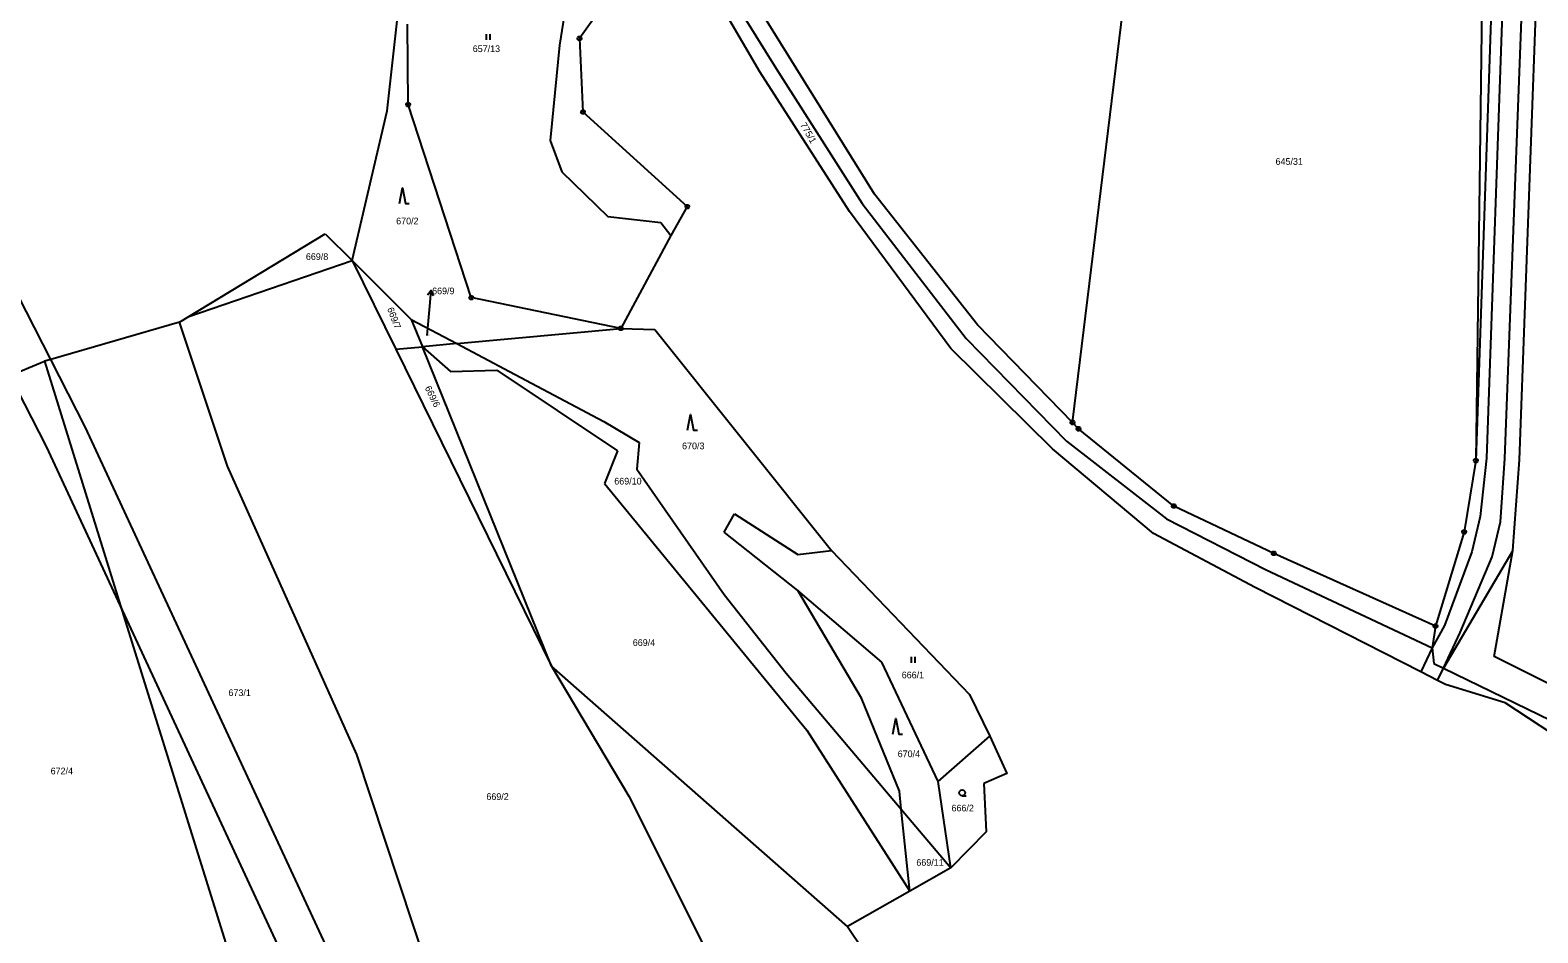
# Model space of a CAD drawing. Extents: x -694465 to -690527, y -983694 to -978978.
# Drawn here: x -693075.3 to -692691.9, y -983133.7 to -982904.1 of the extents above; entities that cross this region are included whole.
import ezdxf

# ---------------------------------------------------------------- set-up
doc = ezdxf.new("R2010")
doc.units = 0
for name, color, linetype in [('Vrstva 1', 7, 'Continuous'), ('Vrstva 16', 7, 'Continuous'), ('Vrstva 18', 7, 'Continuous'), ('Vrstva 24', 7, 'Continuous'), ('Vrstva 25', 7, 'Continuous'), ('Vrstva 29', 7, 'Continuous')]:
    doc.layers.add(name, color=color, linetype=linetype)

msp = doc.modelspace()

# ---------------------------------------------------------------- linework, layer by layer
at = {"layer": 'Vrstva 1'}
for points in [[(-692693.97, -982699.89), (-692705.02, -983012.99)], [(-692700.29, -983013.08), (-692688.43, -982700.11)], [(-693070.091, -982987.841), (-693099.057, -982931.222), (-693137.122, -982864.574), (-693163.283, -982827.058), (-693193.81, -982793.026), (-693210.393, -982777.707)], [(-692701.26, -982824.21), (-692707.71, -983013.6)], [(-692810.28, -983003.89), (-692790.65, -982843.64)], [(-692931.72, -982851.34), (-692940.69, -982907.88)], [(-692705.6, -982853.15), (-692707.71, -983013.6)], [(-692696.6, -983013.38), (-692690.84, -982855.94)], [(-692984.51, -982924.57), (-692976.98, -982856.48)], [(-692924.1, -982890.03), (-692935.65, -982906.19), (-692934.76, -982924.88), (-692908.22, -982948.98), (-692912.43, -982956.3)], [(-692721.73, -983067.37), (-692763.8, -983045.91), (-692789.68, -983032.11), (-692815.36, -983010.62), (-692841.17, -982985.05), (-692866.94, -982950.19), (-692889.77, -982914.71), (-692902.43, -982892.99), (-692902.38, -982890.58)], [(-692898.76, -982892.65), (-692885.65, -982913.87)], [(-692860.66, -982945.81), (-692894.16, -982891.71)], [(-692979.19, -982923.02), (-692979.38, -982902.54)], [(-692940.69, -982907.88), (-692943.13, -982932.17)], [(-692885.65, -982913.87), (-692863.75, -982948.19)], [(-692993.43, -982962.7), (-692984.51, -982924.57)], [(-692963.15, -982972.11), (-692979.19, -982923.02)], [(-692943.13, -982932.17), (-692940.11, -982940.11)], [(-692940.11, -982940.11), (-692928.43, -982951.47)], [(-692834.41, -982979.04), (-692860.66, -982945.81)], [(-692928.43, -982951.47), (-692914.99, -982952.98)], [(-692863.75, -982948.19), (-692837.29, -982982.54)], [(-692914.99, -982952.98), (-692912.43, -982956.3)], [(-693034.95, -982976.94), (-693000.27, -982955.89)], [(-693000.27, -982955.89), (-692993.43, -982962.7)], [(-692912.43, -982956.3), (-692925.14, -982979.97)], [(-693034.95, -982976.94), (-692993.43, -982962.7)], [(-692993.43, -982962.7), (-692982.37, -982985.27)], [(-692993.43, -982962.7), (-692978.41, -982977.65)], [(-692925.14, -982979.97), (-692963.15, -982972.11)], [(-693037.37, -982978.41), (-693070.091, -982987.841)], [(-693037.37, -982978.41), (-693034.95, -982976.94)], [(-693025.12, -983015.04), (-693037.37, -982978.41)], [(-692978.41, -982977.65), (-692975.59, -982984.64)], [(-692978.41, -982977.65), (-692966.79, -982983.83)], [(-692966.79, -982983.83), (-692925.14, -982979.97)], [(-692925.14, -982979.97), (-692916.48, -982980.27)], [(-692916.48, -982980.27), (-692871.52, -983036.45)], [(-692837.29, -982982.54), (-692811.77, -983008.68)], [(-692810.28, -983003.89), (-692834.41, -982979.04)], [(-692982.37, -982985.27), (-692975.59, -982984.64)], [(-692982.37, -982985.27), (-692942.79, -983065.9)], [(-692966.79, -982983.83), (-692975.59, -982984.64)], [(-692942.79, -983065.9), (-692975.59, -982984.64)], [(-692975.59, -982984.64), (-692968.44, -982990.89)], [(-692966.79, -982983.83), (-692953.44, -982990.93)], [(-693080.387, -982991.977), (-693071.72, -982988.31)], [(-693070.091, -982987.841), (-693071.72, -982988.31)], [(-693071.72, -982988.31), (-693052.335, -983050.557)], [(-692955.63, -983208.19), (-692974.61, -983181.207), (-693000.18, -983136.863), (-693061.246, -983005.207), (-693070.091, -982987.841)], [(-693052.335, -983050.557), (-693071.136, -983010.025), (-693080.387, -982991.977)], [(-692968.44, -982990.89), (-692956.67, -982990.6)], [(-692956.67, -982990.6), (-692925.97, -983011.1)], [(-692953.44, -982990.93), (-692929.45, -983003.63)], [(-692929.45, -983003.63), (-692920.47, -983008.96)], [(-692808.73, -983005.5), (-692810.28, -983003.89)], [(-692784.49, -983025.14), (-692808.73, -983005.5)], [(-692920.47, -983008.96), (-692921.02, -983015.79)], [(-692811.77, -983008.68), (-692786.33, -983028.43)], [(-692925.97, -983011.1), (-692929.24, -983019.41)], [(-692705.02, -983012.99), (-692706.63, -983027.79)], [(-692701.44, -983029.14), (-692700.29, -983013.08)], [(-692992.22, -983088.37), (-693025.12, -983015.04)], [(-692921.02, -983015.79), (-692898.84, -983047.69)], [(-692707.71, -983013.6), (-692710.68, -983031.75)], [(-692698.29, -983036.44), (-692696.6, -983013.38)], [(-692929.24, -983019.41), (-692877.84, -983082.18)], [(-692898.88, -983031.77), (-692896.22, -983027.16)], [(-692896.22, -983027.16), (-692880.11, -983037.51)], [(-692786.33, -983028.43), (-692761.22, -983041.31)], [(-692759.09, -983037.2), (-692784.49, -983025.14)], [(-692706.63, -983027.79), (-692708.76, -983036.78)], [(-692880.08, -983046.63), (-692898.88, -983031.77)], [(-692710.68, -983031.75), (-692717.94, -983055.71)], [(-692703.58, -983038.05), (-692701.44, -983029.14)], [(-692880.11, -983037.51), (-692871.52, -983036.45)], [(-692871.52, -983036.45), (-692836.46, -983073.11), (-692831.31, -983083.66)], [(-692717.94, -983055.71), (-692759.09, -983037.2)], [(-692698.29, -983036.44), (-692715.95, -983066.39)], [(-692708.76, -983036.78), (-692715.63, -983055.52)], [(-692711.7, -983057.33), (-692703.58, -983038.05)], [(-692703, -983063.4), (-692698.29, -983036.44)], [(-692761.22, -983041.31), (-692718.8, -983061.2)], [(-692898.84, -983047.69), (-692883.07, -983067.67)], [(-692858.79, -983064.9), (-692880.08, -983046.63)], [(-692863.92, -983074.03), (-692880.08, -983046.63)], [(-693012.431, -983136.594), (-693052.335, -983050.557)], [(-693052.335, -983050.557), (-693022.376, -983146.757)], [(-692715.63, -983055.52), (-692718.8, -983061.2)], [(-692717.94, -983055.71), (-692718.8, -983061.2)], [(-692715.95, -983066.39), (-692711.7, -983057.33)], [(-692718.8, -983061.2), (-692721.73, -983067.37)], [(-692718.8, -983061.2), (-692718.4, -983065.2)], [(-692942.79, -983065.9), (-692923.12, -983098.95)], [(-692867.48, -983132.13), (-692942.79, -983065.9)], [(-692844.44, -983095.26), (-692858.79, -983064.9)], [(-692718.4, -983065.2), (-692715.95, -983066.39)], [(-692717.43, -983069.56), (-692715.95, -983066.39)], [(-692715.95, -983066.39), (-692670.42, -983088.49)], [(-692670.77, -983079.62), (-692703, -983063.4)], [(-692883.07, -983067.67), (-692853.82, -983102.28)], [(-692717.43, -983069.56), (-692721.73, -983067.37)], [(-692670.42, -983088.49), (-692673.28, -983092.95), (-692700.23, -983075.24), (-692715.46, -983070.56), (-692717.43, -983069.56)], [(-692854.3, -983097.7), (-692863.92, -983074.03)], [(-692877.84, -983082.18), (-692851.66, -983123.13)], [(-692844.44, -983095.26), (-692831.31, -983083.66)], [(-692831.31, -983083.66), (-692826.93, -983093.22), (-692832.81, -983095.74)], [(-692956.31, -983197.05), (-692992.22, -983088.37)], [(-692841.22, -983117.2), (-692844.44, -983095.26)], [(-692832.81, -983095.74), (-692832.22, -983108.04), (-692841.22, -983117.2)], [(-692923.12, -983098.95), (-692868.13, -983208.67)], [(-692853.82, -983102.28), (-692854.3, -983097.7)], [(-692853.82, -983102.28), (-692841.22, -983117.2)], [(-692851.66, -983123.13), (-692853.82, -983102.28)], [(-692841.22, -983117.2), (-692851.66, -983123.13)], [(-692851.66, -983123.13), (-692867.48, -983132.13)], [(-692867.48, -983132.13), (-692811.2, -983215.97)]]:
    msp.add_lwpolyline(points, dxfattribs=at)
at = {"layer": 'Vrstva 16'}
msp.add_line((-692974.37, -982981.78), (-692973.73, -982974.26), dxfattribs=at)
at = {"layer": 'Vrstva 24'}
for points in [[(-692935.496, -982905.714), (-692935.246, -982905.896), (-692935.15, -982906.19), (-692935.246, -982906.484), (-692935.496, -982906.666), (-692935.804, -982906.666), (-692936.054, -982906.484), (-692936.15, -982906.19), (-692936.054, -982905.896), (-692935.804, -982905.714)], [(-692979.036, -982922.544), (-692978.786, -982922.726), (-692978.69, -982923.02), (-692978.786, -982923.314), (-692979.036, -982923.496), (-692979.344, -982923.496), (-692979.594, -982923.314), (-692979.69, -982923.02), (-692979.594, -982922.726), (-692979.344, -982922.544)], [(-692934.606, -982924.404), (-692934.356, -982924.586), (-692934.26, -982924.88), (-692934.356, -982925.174), (-692934.606, -982925.356), (-692934.914, -982925.356), (-692935.164, -982925.174), (-692935.26, -982924.88), (-692935.164, -982924.586), (-692934.914, -982924.404)], [(-692908.066, -982948.504), (-692907.816, -982948.686), (-692907.72, -982948.98), (-692907.816, -982949.274), (-692908.066, -982949.456), (-692908.374, -982949.456), (-692908.624, -982949.274), (-692908.72, -982948.98), (-692908.624, -982948.686), (-692908.374, -982948.504)], [(-692962.996, -982971.634), (-692962.746, -982971.816), (-692962.65, -982972.11), (-692962.746, -982972.404), (-692962.996, -982972.586), (-692963.304, -982972.586), (-692963.554, -982972.404), (-692963.65, -982972.11), (-692963.554, -982971.816), (-692963.304, -982971.634)], [(-692924.986, -982979.494), (-692924.736, -982979.676), (-692924.64, -982979.97), (-692924.736, -982980.264), (-692924.986, -982980.446), (-692925.294, -982980.446), (-692925.544, -982980.264), (-692925.64, -982979.97), (-692925.544, -982979.676), (-692925.294, -982979.494)], [(-692810.126, -983003.414), (-692809.876, -983003.596), (-692809.78, -983003.89), (-692809.876, -983004.184), (-692810.126, -983004.366), (-692810.434, -983004.366), (-692810.684, -983004.184), (-692810.78, -983003.89), (-692810.684, -983003.596), (-692810.434, -983003.414)], [(-692808.576, -983005.024), (-692808.326, -983005.206), (-692808.23, -983005.5), (-692808.326, -983005.794), (-692808.576, -983005.976), (-692808.884, -983005.976), (-692809.134, -983005.794), (-692809.23, -983005.5), (-692809.134, -983005.206), (-692808.884, -983005.024)], [(-692707.556, -983013.124), (-692707.306, -983013.306), (-692707.21, -983013.6), (-692707.306, -983013.894), (-692707.556, -983014.076), (-692707.864, -983014.076), (-692708.114, -983013.894), (-692708.21, -983013.6), (-692708.114, -983013.306), (-692707.864, -983013.124)], [(-692784.336, -983024.664), (-692784.086, -983024.846), (-692783.99, -983025.14), (-692784.086, -983025.434), (-692784.336, -983025.616), (-692784.644, -983025.616), (-692784.894, -983025.434), (-692784.99, -983025.14), (-692784.894, -983024.846), (-692784.644, -983024.664)], [(-692710.526, -983031.274), (-692710.276, -983031.456), (-692710.18, -983031.75), (-692710.276, -983032.044), (-692710.526, -983032.226), (-692710.834, -983032.226), (-692711.084, -983032.044), (-692711.18, -983031.75), (-692711.084, -983031.456), (-692710.834, -983031.274)], [(-692758.936, -983036.724), (-692758.686, -983036.906), (-692758.59, -983037.2), (-692758.686, -983037.494), (-692758.936, -983037.676), (-692759.244, -983037.676), (-692759.494, -983037.494), (-692759.59, -983037.2), (-692759.494, -983036.906), (-692759.244, -983036.724)], [(-692717.786, -983055.234), (-692717.536, -983055.416), (-692717.44, -983055.71), (-692717.536, -983056.004), (-692717.786, -983056.186), (-692718.094, -983056.186), (-692718.344, -983056.004), (-692718.44, -983055.71), (-692718.344, -983055.416), (-692718.094, -983055.234)]]:
    msp.add_lwpolyline(points, close=True, dxfattribs=at)
for points in [[(-692935.769, -982906.19), (-692935.53, -982906.19)], [(-692979.309, -982923.02), (-692979.07, -982923.02)], [(-692934.879, -982924.88), (-692934.64, -982924.88)], [(-692908.339, -982948.98), (-692908.1, -982948.98)], [(-692963.269, -982972.11), (-692963.03, -982972.11)], [(-692925.259, -982979.97), (-692925.02, -982979.97)], [(-692810.399, -983003.89), (-692810.16, -983003.89)], [(-692808.849, -983005.5), (-692808.61, -983005.5)], [(-692707.829, -983013.6), (-692707.59, -983013.6)], [(-692784.609, -983025.14), (-692784.37, -983025.14)], [(-692710.799, -983031.75), (-692710.56, -983031.75)], [(-692759.209, -983037.2), (-692758.97, -983037.2)], [(-692718.059, -983055.71), (-692717.82, -983055.71)]]:
    msp.add_lwpolyline(points, dxfattribs=at)
at = {"layer": 'Vrstva 25'}
for points in [[(-692959.38, -982905.06), (-692959.38, -982906.56)], [(-692958.38, -982906.56), (-692958.38, -982905.06)], [(-692981.42, -982948.19), (-692980.67, -982944.19), (-692979.92, -982948.19), (-692978.92, -982948.19)], [(-692908.16, -983005.83), (-692907.41, -983001.83), (-692906.66, -983005.83), (-692905.66, -983005.83)], [(-692851.32, -983063.51), (-692851.32, -983065.01)], [(-692850.32, -983065.01), (-692850.32, -983063.51)], [(-692855.97, -983083.17), (-692855.22, -983079.17), (-692854.47, -983083.17), (-692853.47, -983083.17)], [(-692838.33, -983098.86), (-692838.705, -983098.759), (-692838.979, -983098.485), (-692839.08, -983098.11), (-692838.979, -983097.735), (-692838.705, -983097.461), (-692838.33, -983097.36), (-692837.955, -983097.461), (-692837.681, -983097.735), (-692837.58, -983098.11), (-692837.681, -983098.485), (-692837.955, -983098.759), (-692838.33, -983098.86), (-692837.33, -983098.861)]]:
    msp.add_lwpolyline(points, dxfattribs=at)
at = {"layer": 'Vrstva 29'}
for points in [[(-692973.73, -982974.26), (-692973.39, -982970.275), (-692974.248, -982971.506)], [(-692972.753, -982971.634), (-692973.39, -982970.275)]]:
    msp.add_lwpolyline(points, dxfattribs=at)

# ---------------------------------------------------------------- texts
at = {"layer": 'Vrstva 16'}
msp.add_text('669/9', height=1.7, dxfattribs=at).set_placement((-692973.113, -982971.27))
at = {"layer": 'Vrstva 18'}
for s, height, p in [('657/13', 1.7, (-692962.783, -982909.66)), ('645/31', 1.7, (-692758.633, -982938.34)), ('670/2', 1.7, (-692982.253, -982953.48)), ('669/8', 1.7, (-693005.213, -982962.54)), ('669/9', 0.2, (-692974.328, -982981.78)), ('670/3', 1.7, (-692909.553, -983010.7)), ('669/10', 1.7, (-692926.793, -983019.67)), ('669/4', 1.7, (-692922.083, -983060.74)), ('666/1', 1.7, (-692853.695, -983068.99)), ('673/1', 1.7, (-693024.903, -983073.49)), ('670/4', 1.7, (-692854.723, -983089.04)), ('672/4', 1.7, (-693070.123, -983093.4)), ('669/2', 1.7, (-692959.317, -983099.91)), ('666/2', 1.7, (-692841.037, -983102.84)), ('669/11', 1.7, (-692849.973, -983116.68))]:
    msp.add_text(s, height=height, dxfattribs=at).set_placement(p)
for s, rotation, p in [('775/1', 299.71422, (-692879.583, -982928.15)), ('669/7', 290.71879, (-692984.574, -982974.964)), ('669/6', 296.10459, (-692975.033, -982995.081))]:
    msp.add_text(s, height=1.7, rotation=rotation, dxfattribs=at).set_placement(p)

doc.saveas('drawing.dxf')
